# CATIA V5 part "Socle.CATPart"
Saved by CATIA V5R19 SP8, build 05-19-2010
Part number: Socle
Bounding box of the stored display mesh (mm): x -270 to 25.5, y 0 to 250, z 0 to 150
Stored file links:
  E:\IAO_2010\iao\IAO_MMS_Groupe2\IAO_MMS_Groupe2\OK\nmoissenet\nmoissenet\nmoissenet\Socle.CATPart
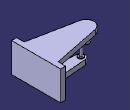
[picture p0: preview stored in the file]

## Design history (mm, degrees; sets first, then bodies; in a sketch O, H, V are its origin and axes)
Body1 (main body)
  Sketch1 on yz-plane, origin (0, 0, 0), H (0, 1, 0), V (0, 0, 1)
    line L1 (0, 0) -> (250, 0)
    line L2 (250, 0) -> (250, 150)
    line L3 (250, 150) -> (0, 150)
    line L4 (0, 150) -> (0, 0)
    length L3 = 250
    length L4 = 150
    horizontal: L1 H, L3 H
    vertical: L2 V, L4 V
  Pad1: profile Sketch1, direction (1, 0, 0), length 25.5
  Sketch2 on face of Pad1 from Sketch1.L3, origin (0, 0, 150), H (1, 0, 0), V (0, 1, 0)
    point P1 (0, 212)
    line L1 (0, 212) -> (-237.8776, 164.2166)
    arc A1 centre (-230, 125) radius 40 from (-237.8776, 164.2166) to (-237.8776, 85.7834) ccw
    point P3 (-230, 125)
    line L2 (-237.8776, 85.7834) -> (0, 38)
    point P5 (0, 38)
    reference projected point E1 (0, 250) from vertex [face of Pad1 from Sketch1.L3 | start face of Pad1 | face of Pad1 from Sketch1.L2]
    reference projected line E2 (0, 250) -> (0, 0) from edge [start face of Pad1 | face of Pad1 from Sketch1.L3]
    reference projected line E3 (0, 250) -> (25.5, 250) from edge [face of Pad1 from Sketch1.L3 | face of Pad1 from Sketch1.L2]
    line L3 (0, 212) -> (0, 38)
    distance P5 H = 38
    distance P1 E1 = 38
    distance P3 E2 = 230
    distance P3 A1 = 40
    distance P3 E3 = 125
    coincidence: P1 V, P5 V
    tangency: A1 L1, L2 A1
    vertical: L3 V
  Pad2: profile Sketch2, direction (0, 0, -1), length 25.5
  Sketch3 on face of Pad1 from Sketch1.L1, origin (0, 0, 0), H (1, 0, 0), V (0, -1, 0)
    point P1 (0, -87)
    line L1 (0, -87) -> (-204.7214, -103.0674)
    arc A1 centre (-203, -125) radius 22 from (-204.7214, -103.0674) to (-204.7214, -146.9326) ccw
    point P3 (-203, -125)
    line L2 (-204.7214, -146.9326) -> (0, -163)
    point P5 (0, -163)
    reference projected line E1 (0, -250) -> (25.5, -250) from edge [face of Pad1 from Sketch1.L2 | face of Pad1 from Sketch1.L1]
    reference projected line E2 (0, 0) -> (0, -250) from edge [start face of Pad1 | face of Pad1 from Sketch1.L1]
    reference projected line E3 (0, -250) -> (25.5, -250) from edge [face of Pad1 from Sketch1.L2 | face of Pad1 from Sketch1.L1]
    line L3 (0, -87) -> (0, -163)
    distance H P1 = 87
    distance P5 E1 = 87
    distance P3 E2 = 203
    distance P3 A1 = 22
    distance P3 E3 = 125
    coincidence: P1 V, P5 V
    tangency: A1 L1, A1 L2
    vertical: L3 V
  Pad3: profile Sketch3, direction (0, 0, 1), length 25.5
  Sketch4 on end face of Pad2, origin (0, 0, 124.5), H (1, 0, 0), V (0, -1, 0)
    circle A1 centre (-230, -125) radius 25.5
    point P1 (-230, -125)
    reference projected line E1 (0, -250) -> (25.5, -250) from edge [face of Pad1 from Sketch1.L2 | face of Pad1 from Sketch1.L1]
    reference projected arc E2 centre (-230, -125) radius 40 from (-237.8776, -85.7834) to (-237.8776, -164.2166) ccw from edge [end face of Pad2 | face of Pad2 from Sketch2.A1]
    distance P1 E1 = 125
    distance P1 E2 = 40
    radius A1 = 25.5
  Pad4: profile Sketch4, direction (0, 0, -1), length 5
  Sketch5 on end face of Pad4, origin (0, 0, 119.5), H (1, 0, 0), V (0, -1, 0)
    circle A1 centre (-230, -125) radius 16.5
    point P1 (-230, -125)
    reference projected arc E1 centre (-230, -125) radius 40 from (-237.8776, -85.7834) to (-237.8776, -164.2166) ccw from edge [end face of Pad2 | face of Pad2 from Sketch2.A1]
    radius A1 = 16.5
    distance P1 H = 125
    distance P1 E1 = 40
  Pad5: profile Sketch5, direction (0, 0, -1), length 40
  Sketch6 on end face of Pad3, origin (0, 0, 25.5), H (1, 0, 0), V (0, 1, 0)
    circle A1 centre (-203, 125) radius 13.5
    point P1 (-203, 125)
    reference projected line E1 (25.5, 250) -> (25.5, 0) from edge [face of Pad1 from Sketch1.L3 | end face of Pad1]
    reference projected line E2 (0, 250) -> (25.5, 250) from edge [face of Pad1 from Sketch1.L3 | face of Pad1 from Sketch1.L2]
    distance P1 E1 = 228.5
    distance P1 E2 = 125
    radius A1 = 13.5
  Pad6: profile Sketch6, direction (0, 0, 1), length 5
  Sketch7 on end face of Pad6, origin (0, 0, 30.5), H (1, 0, 0), V (0, 1, 0)
    circle A1 centre (-203, 125) radius 7.5
    point P1 (-203, 125)
    reference projected line E1 (25.5, 250) -> (25.5, 0) from edge [face of Pad1 from Sketch1.L3 | end face of Pad1]
    reference projected line E2 (0, 250) -> (25.5, 250) from edge [face of Pad1 from Sketch1.L3 | face of Pad1 from Sketch1.L2]
    radius A1 = 7.5
    distance P1 E1 = 228.5
    distance E2 P1 = 125
  Pad7: profile Sketch7, direction (0, 0, 1), length 44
